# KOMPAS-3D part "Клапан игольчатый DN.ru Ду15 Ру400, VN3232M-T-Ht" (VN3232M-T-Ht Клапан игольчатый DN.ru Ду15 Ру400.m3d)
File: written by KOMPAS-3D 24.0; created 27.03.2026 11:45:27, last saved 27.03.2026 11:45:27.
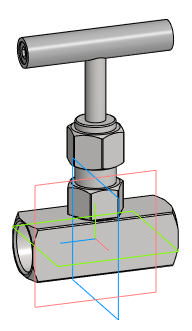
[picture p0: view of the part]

Document properties: Автор: Илья; Полное имя файла: D:\Обмен\Заказы с фриланса\DN.ru\VNxxM-T-Ht Клапан игольчатый DN.ru Ду8-50 Ру400\VN3232M-T-Ht Клапан игольчатый DN.ru Ду8-50 Ру400\DN15\VN3232M-T-Ht Клапан игольчатый DN.ru Ду15 Ру400.m3d

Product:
- Body: Body6  | qty 1
    Масса: 0.282571
- Part/product: Клапан игольчатый DN.ru Ду15 Ру400  | designation VN3232M-T-Ht
    Масса: 0.45
    Раздел спецификации: Прочие изделия
    Примечание: D090-02131

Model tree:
1. Body6  (labels: Body6)

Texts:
  VN3232M-T-Ht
